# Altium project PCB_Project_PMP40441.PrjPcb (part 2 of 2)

## Sheet PMP40442_Main.SchDoc
size 431 x 279 mm; Date: Not shown in title block; ApprovedBy: Not shown in title block; CheckedBy: Not shown in title block; Author: Not shown in title block; CompanyName: Not shown in title block; Engineer: Not shown in title block; Organization: Not shown in title block; Address1: Not shown in title block; Address2: Not shown in title block; Address3: Not shown in title block; Address4: Not shown in title block; DocumentNumber: 2; Revision: Use project parameter SCH_Rev; SheetNumber: 3; SheetTotal: 3; PageSetup: Record=PageOptions¦CenterHorizontal=True¦CenterVertical=True¦PrintScale=1.00¦XCorrection=1.00¦YCorrection=1.00¦PrintKind=0¦BorderSize=5000000¦LeftOffset=0¦BottomOffset=0¦Orientation=2¦PaperLength=1000¦PaperWidth=1000¦Scale=100¦PaperSource=15¦PrintQuality=600¦MediaType=1¦DitherType=10¦PaperKind=Letter¦PrintScaleMode=1
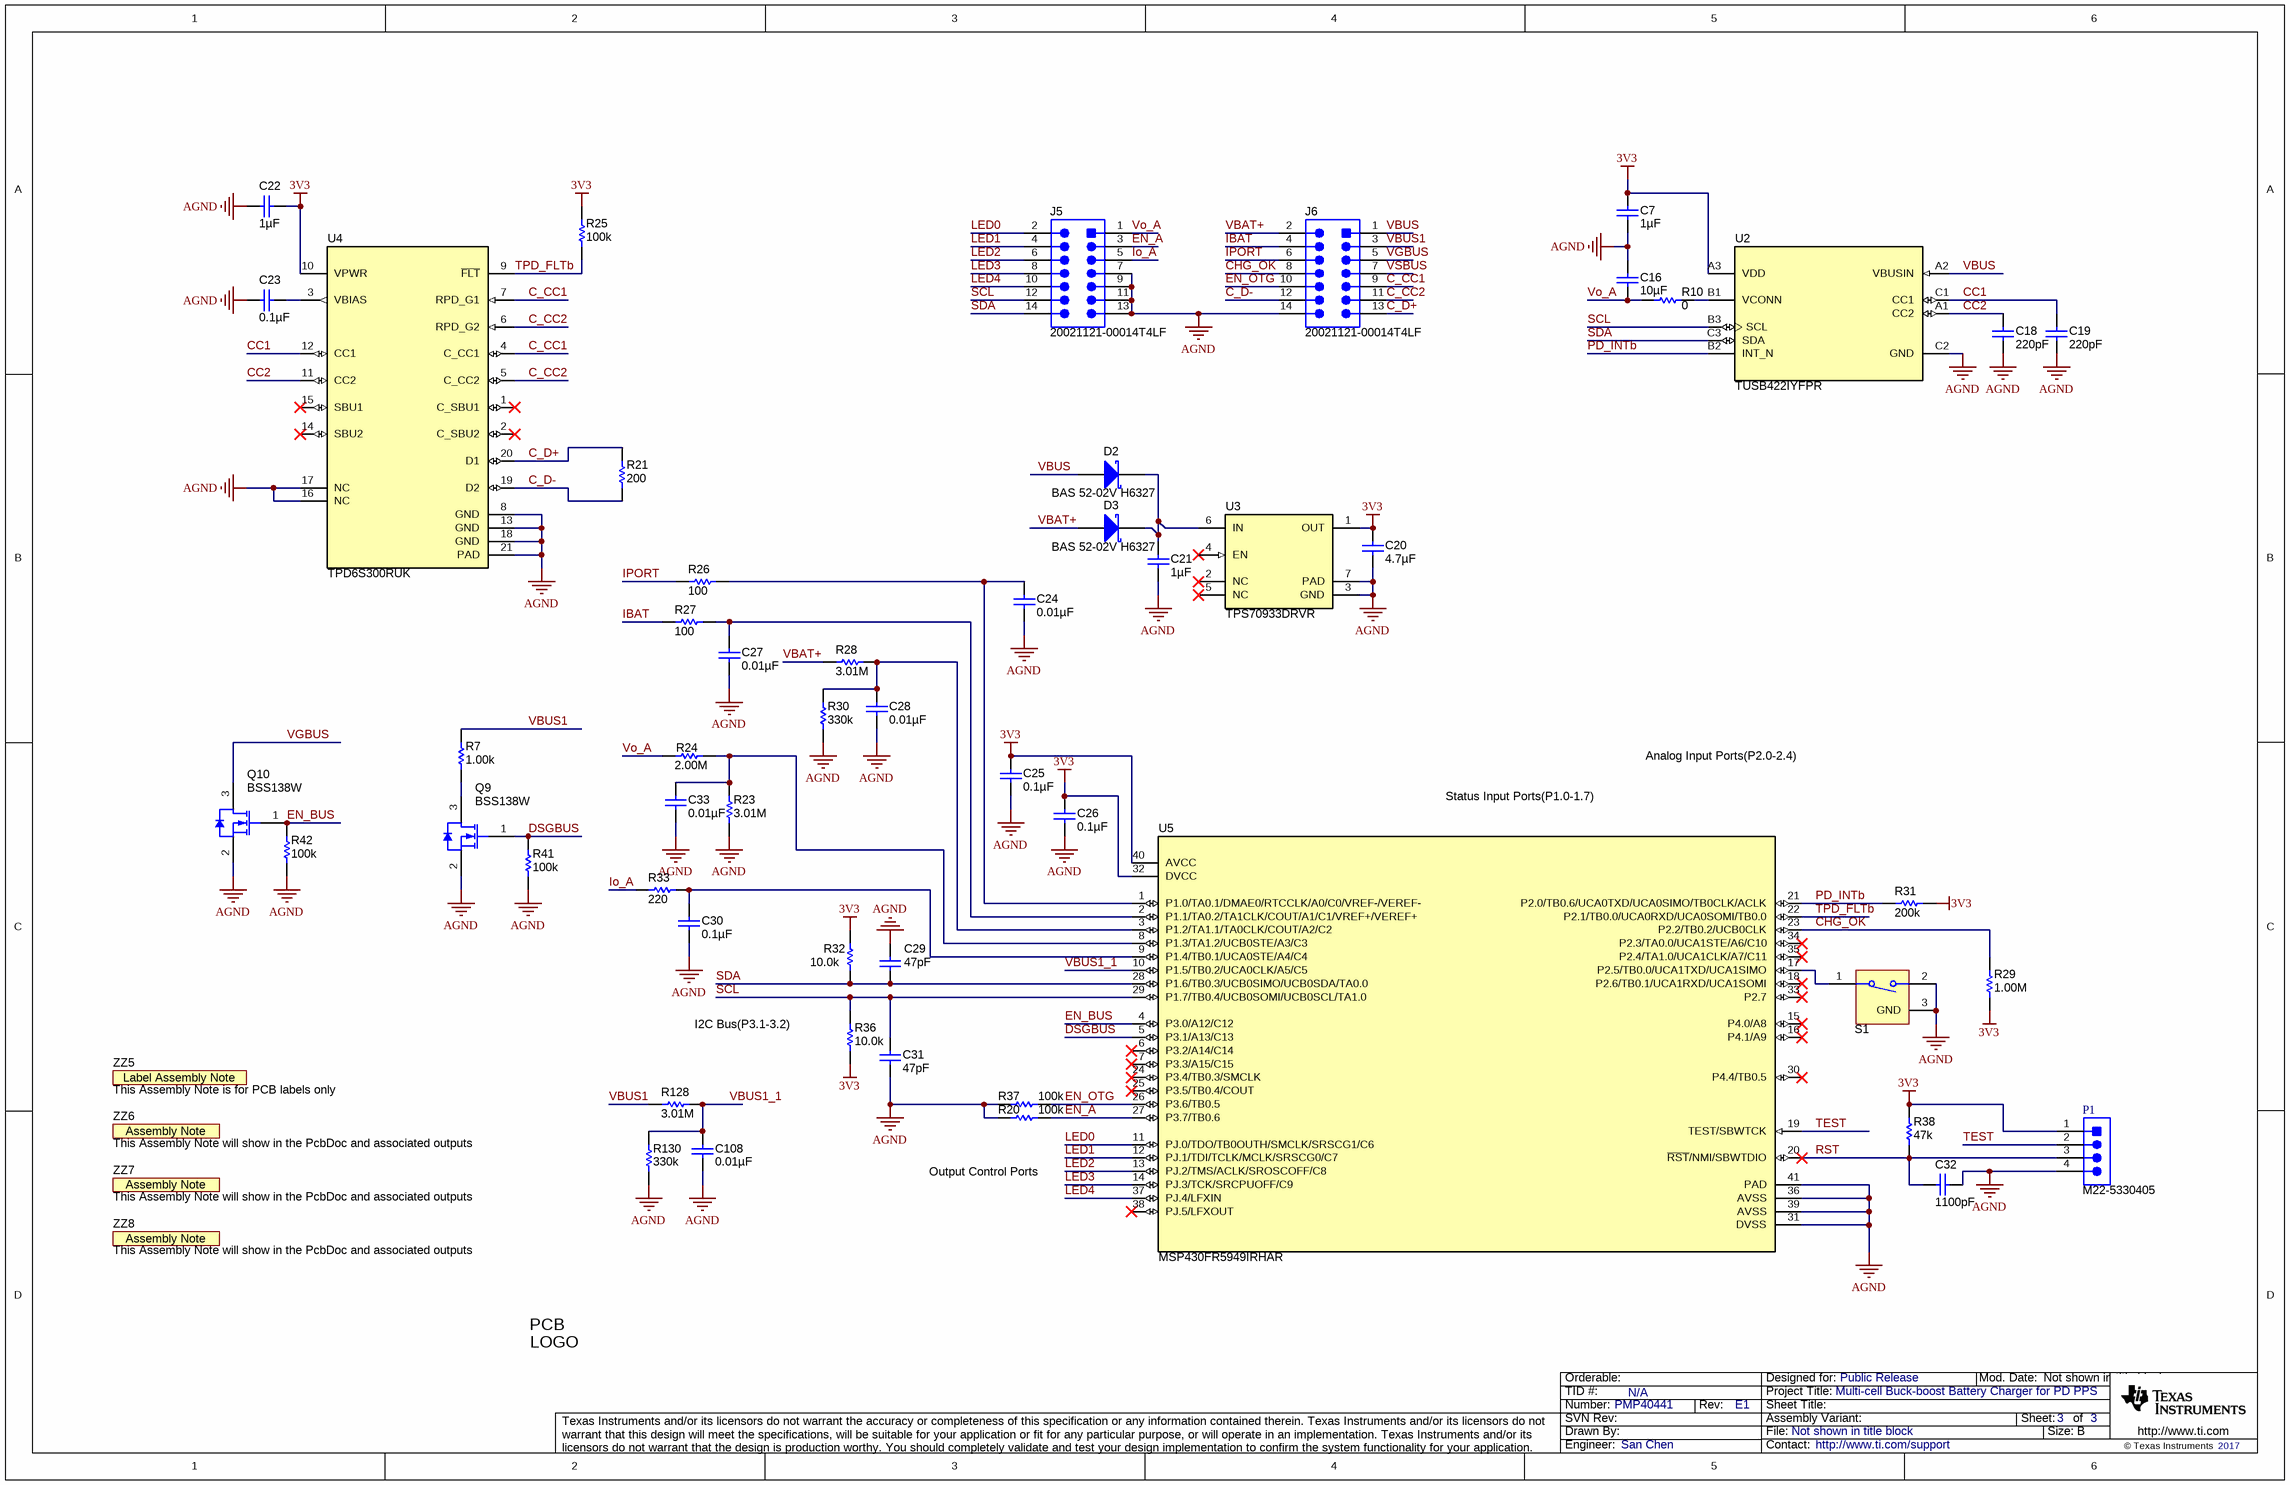
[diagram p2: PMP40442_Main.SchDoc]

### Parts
C7  ValueDisplayed: 1µF  [0402]  (hidden comment: 885012105012)
C16  ValueDisplayed: 10µF  [0402S]  (hidden comment: CL05A106MP5NUNC)
C18  ValueDisplayed: 220pF  [0402S]  (hidden comment: GRM1555C1H221JA01D)
C19  ValueDisplayed: 220pF  [0402]  (hidden comment: GRM1555C1H221JA01D)
C20  ValueDisplayed: 4.7µF  [0402S]  (hidden comment: C1005X5R0J475M050BC)
C21  ValueDisplayed: 1µF  [0402]  (hidden comment: GRM155R6YA105KE11D)
C22  ValueDisplayed: 1µF  [0402]  (hidden comment: 885012105012)
C23  ValueDisplayed: 0.1µF  [0402S]  (hidden comment: GRM155R61H104ME14D)
C24  ValueDisplayed: 0.01µF  [0402]  (hidden comment: GRM155R61C103KA01D)
C25  ValueDisplayed: 0.1µF  [0402]  (hidden comment: C1005X5R1A104K050BA)
C26  ValueDisplayed: 0.1µF  [0402]  (hidden comment: C1005X5R1A104K050BA)
C27  ValueDisplayed: 0.01µF  [0402]  (hidden comment: GRM155R61C103KA01D)
C28  ValueDisplayed: 0.01µF  [0402]  (hidden comment: GRM155R61C103KA01D)
C29  ValueDisplayed: 47pF  [0402]  (hidden comment: GRM1555C1H470FA01D)
C30  ValueDisplayed: 0.1µF  [0402]  (hidden comment: GRM155R61C104KA88D)
C31  ValueDisplayed: 47pF  [0402]  (hidden comment: GRM1555C1H470FA01D)
C32  ValueDisplayed: 1100pF  [0402]  (hidden comment: C0402C112J5GAC7867)
C33  ValueDisplayed: 0.01µF  [0402]  (hidden comment: GRM155R61C103KA01D)
C108  ValueDisplayed: 0.01µF  [0402]  (hidden comment: GRM155R61C103KA01D)
D2  BAS 52-02V H6327  [SOD-523]
D3  BAS 52-02V H6327  [SOD-523]
J5  20021121-00014T4LF  [FCI_20021121-00014x4]
J6  20021121-00014T4LF  [FCI_20021121-00014x4]
Logo5  Pb-Free Symbol  [Pb-Free_Overlay_Small]  (value not drawn)  (no BOM)
P1  M22-5330405  [Harwin_M22-5330405]
Q9  BSS138W  [SOT-323]
Q10  BSS138W  [SOT-323]
R7  ValueDisplayed: 1.00k  [0805_HV]  (hidden comment: CRCW08051K00FKEA)
R10  ValueDisplayed: 0  [0402]  (hidden comment: CRCW04020000Z0ED)
R20  ValueDisplayed: 100k  [0402]  (hidden comment: CRCW0402100KFKED)
R21  ValueDisplayed: 200  [0402]  (hidden comment: CRCW0402200RFKED)
R23  ValueDisplayed: 3.01M  [0402]  (hidden comment: CRCW04023M01FKED)
R24  ValueDisplayed: 2.00M  [0402]  (hidden comment: CRCW04022M00FKED)
R25  ValueDisplayed: 100k  [0402]  (hidden comment: CRCW0402100KJNED)
R26  ValueDisplayed: 100  [0402]  (hidden comment: RC0402FR-07100RL)
R27  ValueDisplayed: 100  [0402]  (hidden comment: RC0402FR-07100RL)
R28  ValueDisplayed: 3.01M  [0402]  (hidden comment: CRCW04023M01FKED)
R29  ValueDisplayed: 1.00M  [0402]  (hidden comment: CRCW04021M00FKED)
R30  ValueDisplayed: 330k  [0402]  (hidden comment: RC0402FR-07330KL)
R31  ValueDisplayed: 200k  [0402]  (hidden comment: CRCW0402200KFKED)
R32  ValueDisplayed: 10.0k  [0402]  (hidden comment: CRCW040210K0FKED)
R33  ValueDisplayed: 220  [0402]  (hidden comment: CRCW0402220RJNED)
R36  ValueDisplayed: 10.0k  [0402]  (hidden comment: CRCW040210K0FKED)
R37  ValueDisplayed: 100k  [0402]  (hidden comment: CRCW0402100KJNED)
R38  ValueDisplayed: 47k  [0402]  (hidden comment: CRCW040247K0JNED)
R41  ValueDisplayed: 100k  [0402]  (hidden comment: CRCW0402100KFKED)
R42  ValueDisplayed: 100k  [0402]  (hidden comment: CRCW0402100KFKED)
R128  ValueDisplayed: 3.01M  [0402]  (hidden comment: CRCW04023M01FKED)
R130  ValueDisplayed: 330k  [0402]  (hidden comment: RC0402FR-07330KL)
S1  B3U-1100P  [SW_B3U-1100P]  (value not drawn)
U2  TUSB422IYFPR  [YFP0009-C01]
U3  TPS70933DRVR  [DRV0006A]
U4  TPD6S300RUK  [RUK0020B]
U5  MSP430FR5949IRHAR  [RHA0040B]
ZZ5  This Assembly Note is for PCB labels only  [AssemblyNoteLabel]  (no BOM)
ZZ6  This Assembly Note will show in the PcbDoc and associated outputs  [AssemblyNote]  (no BOM)
ZZ7  This Assembly Note will show in the PcbDoc and associated outputs  [AssemblyNote]  (no BOM)
ZZ8  This Assembly Note will show in the PcbDoc and associated outputs  [AssemblyNote]  (no BOM)

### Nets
3V3: C7.2 C20.1 C22.2 C25.2 C26.2 P1.1 R25.2 R29.1 R31.1 R32.1 R36.1 R38.2 U2.A3(VDD) U3.1(OUT) U4.10(VPWR) U5.32(DVCC) U5.40(AVCC)
AGND: C7.1 C16.2 C18.1 C19.1 C20.2 C21.1 C22.1 C23.2 C24.2 C25.1 C26.1 C27.2 C28.1 C29.2 C30.2 C31.2 C32.2 C33.1 C108.1 J5.7 J5.9 J5.11 J5.13 J6.14 P1.4 Q9.2(S) Q10.2(S) R20.2 R23.2 R30.1 R37.1 R41.1 R42.1 R130.1 S1.2 S1.3(GND) U2.C2(GND) U3.3(GND) U3.7(PAD) U4.8(GND) U4.13(GND) U4.16(NC) U4.17(NC) U4.18(GND) U4.21(PAD) U5.31(DVSS) U5.36(AVSS) U5.39(AVSS) U5.41(PAD)
VBUS: D2.2(A) J6.1 U2.A2(VBUSIN)
Vo_A: C16.1 J5.1 R10.2 R24.1
C_CC1: J6.9 U4.4(C_CC1) U4.7(RPD_G1)
C_CC2: J6.11 U4.5(C_CC2) U4.6(RPD_G2)
C_D+: J6.13 R21.2 U4.20(D1)
C_D-: J6.12 R21.1 U4.19(D2)
CC1: C19.2 U2.C1(CC1) U4.12(CC1)
CC2: C18.2 U2.A1(CC2) U4.11(CC2)
CHG_OK: J6.8 R29.2 U5.23(P2.2/TB0.2/UCB0CLK)
DSGBUS: Q9.1(G) R41.2 U5.5(P3.1/A13/C13)
EN_A: J5.3 R20.1 U5.27(P3.7/TB0.6)
EN_BUS: Q10.1(G) R42.2 U5.4(P3.0/A12/C12)
EN_OTG: J6.10 R37.2 U5.26(P3.6/TB0.5)
IBAT: J6.4 R27.1
Io_A: J5.5 R33.2
IPORT: J6.6 R26.1
LED0: J5.2 U5.11(PJ.0/TDO/TB0OUTH/SMCLK/SRSCG1/C6)
LED1: J5.4 U5.12(PJ.1/TDI/TCLK/MCLK/SRSCG0/C7)
LED2: J5.6 U5.13(PJ.2/TMS/ACLK/SROSCOFF/C8)
LED3: J5.8 U5.14(PJ.3/TCK/SRCPUOFF/C9)
LED4: J5.10 U5.37(PJ.4/LFXIN)
PD_INTb: R31.2 U2.B2(INT_N) U5.21(P2.0/TB0.6/UCA0TXD/UCA0SIMO/TB0CLK/ACLK)
RST: C32.1 P1.3 R38.1 U5.20(~{RST}/NMI/SBWTDIO)
SCL: C31.1 J5.12 R36.2 U2.B3(SCL) U5.29(P1.7/TB0.4/UCB0SOMI/UCB0SCL/TA1.0)
SDA: C29.1 J5.14 R32.2 U2.C3(SDA) U5.28(P1.6/TB0.3/UCB0SIMO/UCB0SDA/TA0.0)
TEST: P1.2 U5.19(TEST/SBWTCK)
TPD_FLTb: R25.1 U4.9(~{FLT}) U5.22(P2.1/TB0.0/UCA0RXD/UCA0SOMI/TB0.0)
VBAT+: D3.2(A) J6.2 R28.2
VBUS1: J6.3 R7.2 R128.2
VBUS1_1: C108.2 R128.1 R130.2 U5.10(P1.5/TB0.2/UCA0CLK/A5/C5)
VGBUS: J6.5 Q10.3(D)
VSBUS: J6.7
NetC21_2: C21.2 D2.1(K) D3.1(K) U3.6(IN)
NetC23_1: C23.1 U4.3(VBIAS)
NetC24_1: C24.1 R26.2 U5.1(P1.0/TA0.1/DMAE0/RTCCLK/A0/C0/VREF-/VEREF-)
NetC27_1: C27.1 R27.2 U5.2(P1.1/TA0.2/TA1CLK/COUT/A1/C1/VREF+/VEREF+)
NetC28_2: C28.2 R28.1 R30.2 U5.3(P1.2/TA1.1/TA0CLK/COUT/A2/C2)
NetC30_1: C30.1 R33.1 U5.9(P1.4/TB0.1/UCA0STE/A4/C4)
NetC33_2: C33.2 R23.1 R24.2 U5.8(P1.3/TA1.2/UCB0STE/A3/C3)
NetQ9_3: Q9.3(D) R7.1
NetR10_1: R10.1 U2.B1(VCONN)
NetS1_1: S1.1 U5.17(P2.5/TB0.0/UCA1TXD/UCA1SIMO)

Not connected (* = marked no-connect by the designer): U3 2(NC)* 4(EN)* 5(NC)*; U4 1(C_SBU1)* 2(C_SBU2)* 14(SBU2)* 15(SBU1)*; U5 6(P3.2/A14/C14)* 7(P3.3/A15/C15)* 15(P4.0/A8)* 16(P4.1/A9)* 18(P2.6/TB0.1/UCA1RXD/UCA1SOMI)* 24(P3.4/TB0.3/SMCLK)* 25(P3.5/TB0.4/COUT)* 30(P4.4/TB0.5)* 33(P2.7)* 34(P2.3/TA0.0/UCA1STE/A6/C10)* 35(P2.4/TA1.0/UCA1CLK/A7/C11)* 38(PJ.5/LFXOUT)*

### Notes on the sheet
- Analog Input Ports(P2.0-2.4)
- Status Input Ports(P1.0-1.7)
- I2C Bus(P3.1-3.2)
- Output Control Ports

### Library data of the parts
C7 C22 = 885012105012: CAP, CERM, 1 µF, 10 V,+/- 20%, X5R, 0402; Manufacturer: Wurth Elektronik; Polarized: N; CompType: Capacitor; Value: 1uF; U/M: EA; Cap_F: 0.000001; Tolerance_%: 20; VDC_V: 10; Value2: 10V; TaMin_C: -55; TaMax_C: 85; AEC Category: Q200; SizeArea_mm2: 0.5; SizeAreaWB_mm2: 3; SizeX_mm: 1; SizeZ_mm: 0.6
C16 = CL05A106MP5NUNC: CAP, CERM, 10 µF, 10 V,+/- 20%, X5R, 0402; Manufacturer: Samsung Electro-Mechanics; Polarized: N; CompType: Capacitor; Value: 10uF; U/M: EA; Cap_F: 0.00001; Tolerance_%: 20; VDC_V: 10; Value2: 10V; TaMin_C: -55; TaMax_C: 85; Cap_Case: 0402; AEC Category: Q200; SizeArea_mm2: 0.5; SizeAreaWB_mm2: 3; SizeX_mm: 1; SizeZ_mm: 0.6; Green_Lifecycle: Active; Green_REACh: Passed
C18 = GRM1555C1H221JA01D: CAP, CERM, 220 pF, 50 V,+/- 5%, C0G/NP0, 0402; Manufacturer: MuRata; Polarized: N; CompType: Capacitor; Value: 220pF; U/M: EA; Cap_F: 0.00000000022; Tolerance_%: 5; VDC_V: 50; Value2: 50V; TaMin_C: -55; TaMax_C: 125; Cap_Case: 0402; AEC Category: Q200; SizeArea_mm2: 0.5; SizeAreaWB_mm2: 3; SizeX_mm: 1; SizeZ_mm: 0.6; Green_Lifecycle: Active; Green_REACh: Passed
C19 = GRM1555C1H221JA01D: CAP, CERM, 220 pF, 50 V,+/- 5%, C0G/NP0, 0402; Manufacturer: MuRata; Polarized: N; CompType: Capacitor; Value: 220pF; U/M: EA; Cap_F: 0.00000000022; Tolerance_%: 5; VDC_V: 50; Value2: 50V; TaMin_C: -55; TaMax_C: 125; AEC Category: Q200; SizeArea_mm2: 0.5; SizeAreaWB_mm2: 3; SizeX_mm: 1; SizeZ_mm: 0.6; Green_Lifecycle: Active; Green_REACh: Passed
C20 = C1005X5R0J475M050BC: CAP, CERM, 4.7 µF, 6.3 V, +/- 20%, X5R, 0402; Manufacturer: TDK; Polarized: N; CompType: Capacitor; Value: 4.7uF; U/M: EA; Cap_F: 0.0000047; Tolerance_%: 20; Value1: Unknown; VDC_V: 6.3; Value2: 6.3V; TaMin_C: -55; TaMax_C: 85; Cap_Case: 0402
C21 = GRM155R6YA105KE11D: CAP, CERM, 1 µF, 35 V, +/- 10%, X5R, 0402; Manufacturer: MuRata; Polarized: N; CompType: Capacitor; Value: 1uF; U/M: EA; Cap_F: 0.000001; Tolerance_%: 10; Value1: Unknown; VDC_V: 35; Value2: 35V; TaMin_C: -55; TaMax_C: 85; AEC Category: Q200
C23 = GRM155R61H104ME14D: CAP, CERM, 0.1 µF, 50 V, +/- 20%, X5R, 0402; Manufacturer: MuRata; Polarized: N; CompType: Capacitor; Value: 0.1uF; U/M: EA; Cap_F: 0.0000001; Tolerance_%: 20; Value1: Unknown; VDC_V: 50; Value2: 50V; TaMin_C: -55; TaMax_C: 85; Cap_Case: 0402; AEC Category: Q200
C24 C27 C28 C33 C108 = GRM155R61C103KA01D: CAP, CERM, 0.01 µF, 16 V,+/- 10%, X5R, 0402; Manufacturer: MuRata; Polarized: N; CompType: Capacitor; Value: 0.01uF; U/M: EA; Cap_F: 0.00000001; Tolerance_%: 10; VDC_V: 16; Value2: 16V; TaMin_C: -55; TaMax_C: 85; AEC Category: Q200; SizeArea_mm2: 0.5; SizeAreaWB_mm2: 3; SizeX_mm: 1; SizeZ_mm: 0.6
C25 C26 = C1005X5R1A104K050BA: CAP, CERM, 0.1 µF, 10 V, +/- 10%, X5R, 0402; Manufacturer: TDK; Polarized: N; CompType: Capacitor; Value: 0.1uF; U/M: EA; Cap_F: 0.0000001; Tolerance_%: 10; Value1: Unknown; Value2: 10V; TaMin_C: -55; TaMax_C: 85; AEC Category: Q200
C29 C31 = GRM1555C1H470FA01D: CAP, CERM, 47 pF, 50 V, +/- 1%, C0G/NP0, 0402; Manufacturer: MuRata; Polarized: N; CompType: Capacitor; Value: 47pF; U/M: EA; Cap_F: 0.000000000047; Tolerance_%: 1; Value1: Unknown; VDC_V: 50; Value2: 50V; TaMin_C: -55; TaMax_C: 125; AEC Category: Q200
C30 = GRM155R61C104KA88D: CAP, CERM, 0.1 µF, 16 V, +/- 10%, X5R, 0402; Manufacturer: MuRata; Polarized: N; CompType: Capacitor; Value: 0.1uF; U/M: EA; Cap_F: 0.0000001; Tolerance_%: 10; Value1: Unknown; VDC_V: 16; Value2: 16V; TaMin_C: -55; TaMax_C: 85; AEC Category: Q200
C32 = C0402C112J5GAC7867: CAP, CERM, 1100 pF, 50 V, +/- 5%, C0G/NP0, 0402; Manufacturer: Kemet; Polarized: N; CompType: Capacitor; Value: 1100pF; U/M: EA; Cap_F: 0.0000000011; Tolerance_%: 5; Value1: Unknown; VDC_V: 50; Value2: 50V; TaMin_C: -55; TaMax_C: 125; AEC Category: Q200
D2 D3 = BAS 52-02V H6327: Diode, Schottky, 45 V, 0.75 A, SOD-523; Manufacturer: Infineon Technologies; U/M: EA; Vf_V: 0.6; Value: 45V; Value1: 0.75A; Value2: 0.6V; Io_A: 0.75; Vr_V: 45; TJmax_C: 150; AEC Category: Q101
J5 J6 = 20021121-00014T4LF: Header, 1.27 mm, 7x2, Au, SMT; Manufacturer: FCI; SymbolCreator: a0412235
Logo5 = Pb-Free: SymbolCreator: a0412235
P1 = M22-5330405: Header, 2mm, 4x1, Gold, Black, R/A, SMT; Manufacturer: Harwin; SymbolCreator: a0412235; U/M: EA
Q9 Q10 = BSS138W: MOSFET, N-CH, 50 V, 0.21 A, SOT-323; Manufacturer: Fairchild Semiconductor; Alternate Manufacturer: None; U/M: EA; ChType: N; Value: 50V; VdsMax_V: 50; Value1: 6 ohm; Rdson45_ohm: 6; Value2: 1.1 nC; QgTyp_nC: 1.1; Vgs_V: 20; IdsMax_A: 0.21; SizeAreaWB_mm2: 10.24; SizeArea_mm2: 4.84; SizeX_mm: 2.2; AEC Category: Q101; Green_Lifecycle: Active; Green_REACh: Passed
R7 = CRCW08051K00FKEA: RES, 1.00 k, 1%, 0.125 W, 0805; Manufacturer: Vishay-Dale; CompType: Resistor; Value: 1.00k; U/M: EA; Res_ohm: 1000; Value_Code: 1k00; Tolerance_%: 1; Power_W: 0.125; Value2: 0.125W; VDC_V: 150; TempCo: 100 ppm/C; EIA_Code: E96; AEC Category: Q200; SizeArea_mm2: 2.5; SizeX_mm: 2; SizeY_mm: 1.25; SizeZ_mm: 1.45; Green_Lifecycle: Active; Green_REACh: Passed
R10 = CRCW04020000Z0ED: RES, 0, 5%, 0.063 W, 0402; Manufacturer: Vishay-Dale; CompType: Resistor; Value: 0; U/M: EA; Value_Code: 0000; Tolerance_%: 5; Power_W: 0.063; Value2: 0.063W; VDC_V: 50; TempCo: 200 ppm/C; EIA_Code: E24; AEC Category: Q200; SizeArea_mm2: 0.5; SizeX_mm: 1; SizeZ_mm: 0.6; Green_Lifecycle: Active; Green_REACh: Passed
R20 R41 R42 = CRCW0402100KFKED: RES, 100 k, 1%, 0.063 W, 0402; Manufacturer: Vishay-Dale; CompType: Resistor; Value: 100k; U/M: EA; Res_ohm: 100000; Tolerance_%: 1; Power_W: 0.063; Value2: 0.063W; VDC_V: 50; TempCo: 100 ppm/C; EIA_Code: E96; AEC Category: Q200; SizeArea_mm2: 0.5; SizeZ_mm: 0.6; Green_Lifecycle: Active; Green_REACh: Passed
R21 = CRCW0402200RFKED: RES, 200, 1%, 0.063 W, 0402; Manufacturer: Vishay-Dale; CompType: Resistor; Value: 200; U/M: EA; Value_Code: 200R; Tolerance_%: 1; Power_W: 0.063; Value2: 0.063W; VDC_V: 50; TempCo: 100 ppm/C; EIA_Code: E96; AEC Category: Q200; SizeArea_mm2: 0.5; SizeZ_mm: 0.6; Green_Lifecycle: Active; Green_REACh: Passed
R23 R28 R128 = CRCW04023M01FKED: RES, 3.01 M, 1%, 0.063 W, 0402; Manufacturer: Vishay-Dale; CompType: Resistor; Value: 3.01Meg; U/M: EA; Res_ohm: 3010000; Value_Code: 3M01; Tolerance_%: 1; Power_W: 0.063; Value2: 0.063W; VDC_V: 50; TempCo: 100 ppm/C; EIA_Code: E96; AEC Category: Q200; SizeArea_mm2: 0.5; SizeZ_mm: 0.6
R24 = CRCW04022M00FKED: RES, 2.00 M, 1%, 0.063 W, 0402; Manufacturer: Vishay-Dale; CompType: Resistor; Value: 2.00Meg; U/M: EA; Res_ohm: 2000000; Value_Code: 2M00; Tolerance_%: 1; Power_W: 0.063; Value2: 0.063W; VDC_V: 50; TempCo: 100 ppm/C; EIA_Code: E96; AEC Category: Q200; SizeArea_mm2: 0.5; SizeZ_mm: 0.6
R25 = CRCW0402100kJNED: RES, 100 k, 5%, 0.063 W, 0402; Manufacturer: Vishay-Dale; CompType: Resistor; Value: 100k; U/M: EA; Res_ohm: 100000; Tolerance_%: 5; Power_W: 0.063; Value2: 0.063W; VDC_V: 50; TempCo: 200 ppm/C; EIA_Code: E24; AEC Category: Q200
R26 R27 = RC0402FR-07100RL: RES, 100, 1%, 0.063 W, 0402; Manufacturer: Yageo America; CompType: Resistor; Value: 100; U/M: EA; Value_Code: 100R; Tolerance_%: 1; Power_W: 0.063; Value2: 0.063W; VDC_V: 50; TempCo: 100 ppm/C; EIA_Code: E96; SizeArea_mm2: 0.5; SizeZ_mm: 0.6; AEC Category: Q200; AEC Qualified: N; Green_Lifecycle: Active; Green_REACh: Passed
R29 = CRCW04021M00FKED: RES, 1.00 M, 1%, 0.063 W, 0402; Manufacturer: Vishay-Dale; CompType: Resistor; Value: 1.00Meg; U/M: EA; Res_ohm: 1000000; Value_Code: 1M00; Tolerance_%: 1; Power_W: 0.063; Value2: 0.063W; VDC_V: 50; TempCo: 100 ppm/C; EIA_Code: E96; AEC Category: Q200; SizeArea_mm2: 0.5; SizeZ_mm: 0.6; Green_Lifecycle: Active; Green_REACh: Passed
R30 R130 = CMP-0026731-1: RES, 330 k, 1%, 0.0625 W, 0402; Manufacturer: Yageo America; Power_W: 62.5mW; TempCo: 100 ppm/C; U/M: EA; Value: 330k; SizeX_mm: 1; SizeY_mm: 0.5; SizeZ_mm: 0.6; AEC Qualified: N; VDC_V: 50V; AEC Category: Q200
R31 = CRCW0402200KFKED: RES, 200 k, 1%, 0.063 W, 0402; Manufacturer: Vishay-Dale; CompType: Resistor; Value: 200k; U/M: EA; Res_ohm: 200000; Tolerance_%: 1; Power_W: 0.063; Value2: 0.063W; VDC_V: 50; TempCo: 100 ppm/C; EIA_Code: E96; AEC Category: Q200; SizeArea_mm2: 0.5; SizeZ_mm: 0.6; Green_Lifecycle: Active; Green_REACh: Passed
R32 R36 = CRCW040210K0FKED: RES, 10.0 k, 1%, 0.063 W, 0402; Manufacturer: Vishay-Dale; CompType: Resistor; Value: 10.0k; U/M: EA; Res_ohm: 10000; Value_Code: 10k0; Tolerance_%: 1; Power_W: 0.063; Value2: 0.063W; VDC_V: 50; TempCo: 100 ppm/C; EIA_Code: E96; AEC Category: Q200; SizeArea_mm2: 0.5; SizeZ_mm: 0.6; Green_Lifecycle: Active; Green_REACh: Passed
R33 = CRCW0402220RJNED: RES, 220, 5%, 0.063 W, 0402; Manufacturer: Vishay-Dale; CompType: Resistor; Value: 220; U/M: EA; Value_Code: 220R; Tolerance_%: 5; Power_W: 0.063; Value2: 0.063W; VDC_V: 50; TempCo: 200 ppm/C; EIA_Code: E24
R37 = CRCW0402100KJNED: RES, 100 k, 5%, 0.063 W, 0402; Manufacturer: Vishay-Dale; CompType: Resistor; Value: 100k; U/M: EA; Res_ohm: 100000; Tolerance_%: 5; Power_W: 0.063; Value2: 0.063W; VDC_V: 50; TempCo: 200 ppm/C; EIA_Code: E24; AEC Category: Q200
R38 = CRCW040247K0JNED: RES, 47 k, 5%, 0.063 W, 0402; Manufacturer: Vishay-Dale; CompType: Resistor; Value: 47k; U/M: EA; Res_ohm: 47000; Value_Code: 47k0; Tolerance_%: 5; Power_W: 0.063; Value2: 0.063W; VDC_V: 50; TempCo: 200 ppm/C; EIA_Code: E24; AEC Category: Q200
S1 = B3U-1100P: Switch, SPST-NO, Off-Mom, 12 V, SMD; Manufacturer: Omron Electronic Components; SymbolCreator: Altium; VDC_V: 12; PositionCount: 1; CurrentRating_mA: 50
U2 = CMP-0081747-1: USB PD TCPCi Port Controller, YFP0009-C01 (DSBGA-9); Alternate PartNumber: TUSB422IYFPT; Manufacturer: Texas Instruments; SizeArea_mm2: 1.8423; SizeAreaWB_mm2: 5.5573; SizeX_mm: 1.38; SizeY_mm: 1.335; SizeZ_mm: 0.5; CompType: IC; Rating: Catalog; AEC Qualified: N; AEC Category: Q200
U3 = TPS70933DRVR: 150-mA, 30-V, Ultra-Low IQ, Wide Input Low-Dropout Regulator with Reverse Current Protection, DRV0006A (WSON-6); Manufacturer: Texas Instruments; Alternate PartNumber: TPS70933DRVT; SymbolCreator: a0411947; SizeArea_mm2: 4; SizeAreaWB_mm2: 9; SizeX_mm: 2; SizeZ_mm: 0.8; CompType: IC; U/M: EA
U4 = TPD6S300RUK: USB Type C Interface Protector: Short-to-VBUS Over Voltage and IEC 61000-4-2 ESD Protection, RUK0020B; Manufacturer: Texas Instruments; SymbolCreator: a0411947; SizeX_mm: 3; SizeZ_mm: 0.8; CompType: IC; U/M: EA
U5 = MSP430FR5949IRHAR: MSP430FR5949 16 MHz Ultra-Low-Power Microcontroller featuring 64 KB FRAM, 2 KB SRAM, 33 IO, RHA0040B (VQFN-40); Alternate PartNumber: MSP430FR5949IRHAT; Manufacturer: Texas Instruments; SymbolCreator: Altium; CompType: IC; U/M: EA; SizeArea_mm2: 37.8225; SizeAreaWB_mm2: 66.4225; SizeX_mm: 6.15; SizeZ_mm: 1
ZZ5 = AssemblyNoteLabel: SymbolCreator: a0412235
ZZ6-ZZ8 = AssemblyNote: SymbolCreator: codlsc

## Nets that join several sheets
AGND: PMP40441_Main (11 pins), PMP40442_Main (49 pins)
VBUS: PMP40441_Main (13 pins), PMP40442_Main (D2.2 J6.1 U2.A2)
Vo_A: PMP40441_Main (11 pins), PMP40442_Main (C16.1 J5.1 R10.2 R24.1)
C_CC1: PMP40441_Main (J1.A5 J3.9), PMP40442_Main (J6.9 U4.4 U4.7)
C_CC2: PMP40441_Main (J1.B5 J3.11), PMP40442_Main (J6.11 U4.5 U4.6)
C_D+: PMP40441_Main (J1.A6 J1.B6 J3.13), PMP40442_Main (J6.13 R21.2 U4.20)
C_D-: PMP40441_Main (J1.A7 J1.B7 J3.12), PMP40442_Main (J6.12 R21.1 U4.19)
CHG_OK: PMP40441_Main (J3.8 U1.4), PMP40442_Main (J6.8 R29.2 U5.23)
EN_A: PMP40441_Main (J2.3 U8.13), PMP40442_Main (J5.3 R20.1 U5.27)
EN_OTG: PMP40441_Main (J3.10 U1.5), PMP40442_Main (J6.10 R37.2 U5.26)
IBAT: PMP40441_Main (C153.1 J3.4 U1.9), PMP40442_Main (J6.4 R27.1)
Io_A: PMP40441_Main (J2.5 R113.1), PMP40442_Main (J5.5 R33.2)
IPORT: PMP40441_Main (C152.1 J3.6 R98.1 U1.8), PMP40442_Main (J6.6 R26.1)
LED0: PMP40441_Main (J2.2 R104.2), PMP40442_Main (J5.2 U5.11)
LED1: PMP40441_Main (J2.4 R103.2), PMP40442_Main (J5.4 U5.12)
LED2: PMP40441_Main (J2.6 R102.2), PMP40442_Main (J5.6 U5.13)
LED3: PMP40441_Main (J2.8 R101.2), PMP40442_Main (J5.8 U5.14)
LED4: PMP40441_Main (J2.10 R100.2), PMP40442_Main (J5.10 U5.37)
SCL: PMP40441_Main (J2.12 U1.13), PMP40442_Main (5 pins)
SDA: PMP40441_Main (J2.14 U1.12), PMP40442_Main (5 pins)
VBAT+: PMP40441_Main (8 pins), PMP40442_Main (D3.2 J6.2 R28.2)
VBUS1: PMP40441_Main (15 pins), PMP40442_Main (J6.3 R7.2 R128.2)
VGBUS: PMP40441_Main (J3.5 R22.2 R122.2), PMP40442_Main (J6.5 Q10.3)
VSBUS: PMP40441_Main (11 pins), PMP40442_Main (J6.7)

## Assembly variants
001: not fitted FID1 FID2 FID3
